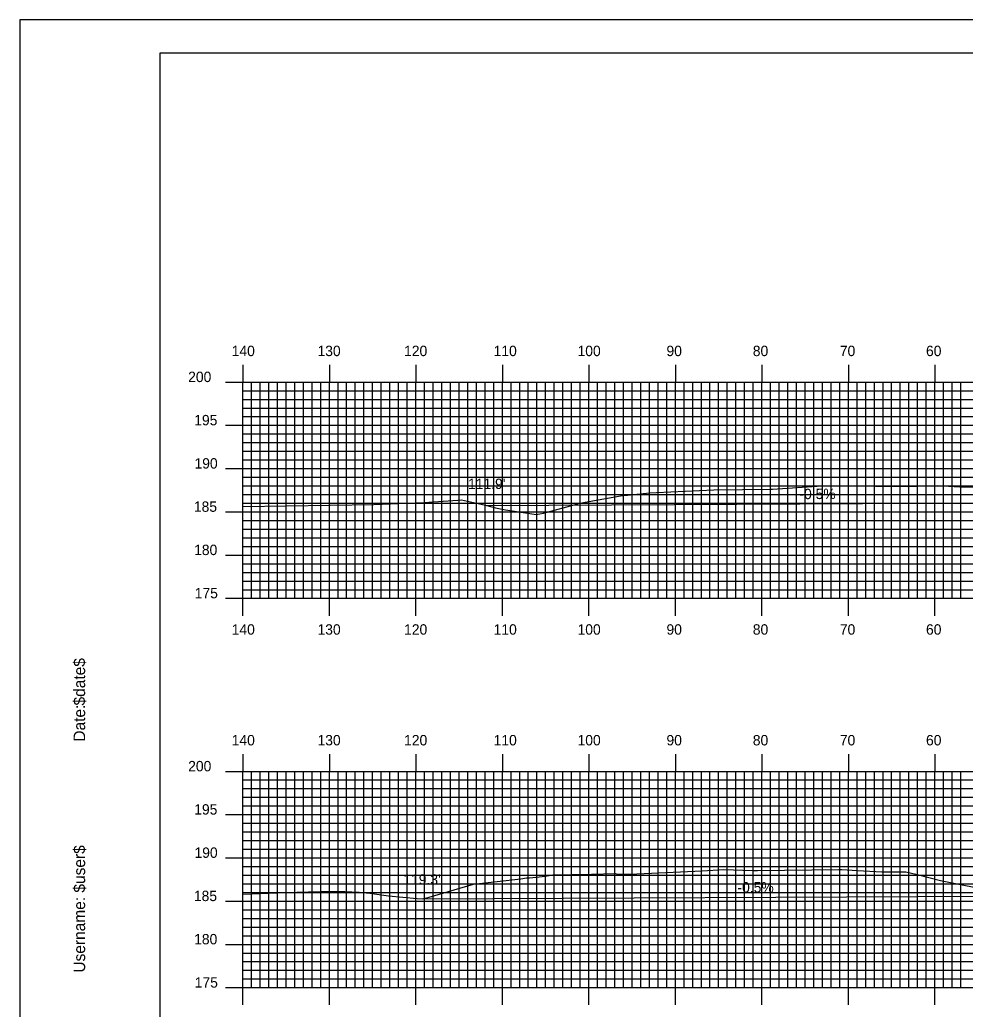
# Model space of a CAD drawing. Extents: x 1822785 to 1823129, y 442591 to 442811.
# Drawn here: x 1822785.5 to 1822894.8, y 442696.2 to 442810.5 of the extents above; entities that cross this region are included whole.
import ezdxf

# ---------------------------------------------------------------- set-up
doc = ezdxf.new("R2010")
doc.units = 0
for name, color, linetype in [('ANNOTATION', 7, 'Continuous'), ('BORDER', 7, 'Continuous'), ('D_Text_Standard', 7, 'Continuous'), ('H_V ANNOTATION', 7, 'Continuous'), ('MAJOR', 7, 'Continuous'), ('MINOR', 7, 'Continuous'), ('PLOT BOUNDARY', 7, 'Continuous'), ('S_Roadway_Centerline', 7, 'Continuous')]:
    doc.layers.add(name, color=color, linetype=linetype)

msp = doc.modelspace()

# ---------------------------------------------------------------- linework, layer by layer
at = {"layer": 'ANNOTATION'}
for p, q in [((1822839.41, 442754.41), (1822916.5, 442754.8)), ((1822832.01, 442708.93), (1822909.57, 442709.32))]:
    msp.add_line(p, q, dxfattribs=at)
at = {"layer": 'BORDER'}
msp.add_lwpolyline([(1822801.68, 442596.67), (1823121.68, 442596.67), (1823121.68, 442806.67), (1822801.68, 442806.67)], close=True, dxfattribs=at)
at = {"layer": 'MAJOR'}
for p, q in [((1822811.28, 442770.67), (1822811.28, 442768.67)), ((1822821.28, 442770.67), (1822821.28, 442768.67)), ((1822831.28, 442770.67), (1822831.28, 442768.67)), ((1822841.28, 442770.67), (1822841.28, 442768.67)), ((1822851.28, 442770.67), (1822851.28, 442768.67)), ((1822861.28, 442770.67), (1822861.28, 442768.67)), ((1822871.28, 442770.67), (1822871.28, 442768.67)), ((1822881.28, 442770.67), (1822881.28, 442768.67)), ((1822891.28, 442770.67), (1822891.28, 442768.67)), ((1822809.28, 442768.67), (1822811.28, 442768.67)), ((1822811.28, 442768.67), (1823091.28, 442768.67)), ((1822811.28, 442743.67), (1822811.28, 442768.67)), ((1822811.28, 442743.67), (1822811.28, 442768.67)), ((1822811.28, 442768.67), (1823091.28, 442768.67)), ((1822821.28, 442743.67), (1822821.28, 442768.67)), ((1822831.28, 442743.67), (1822831.28, 442768.67)), ((1822841.28, 442743.67), (1822841.28, 442768.67)), ((1822851.28, 442743.67), (1822851.28, 442768.67)), ((1822861.28, 442743.67), (1822861.28, 442768.67)), ((1822871.28, 442743.67), (1822871.28, 442768.67)), ((1822881.28, 442743.67), (1822881.28, 442768.67)), ((1822891.28, 442743.67), (1822891.28, 442768.67)), ((1822809.28, 442763.67), (1822811.28, 442763.67)), ((1822811.28, 442763.67), (1823091.28, 442763.67)), ((1822809.28, 442758.67), (1822811.28, 442758.67)), ((1822811.28, 442758.67), (1823091.28, 442758.67)), ((1822809.28, 442753.67), (1822811.28, 442753.67)), ((1822811.28, 442753.67), (1823091.28, 442753.67)), ((1822809.28, 442748.67), (1822811.28, 442748.67)), ((1822811.28, 442748.67), (1823091.28, 442748.67)), ((1822809.28, 442743.67), (1822811.28, 442743.67)), ((1822811.28, 442743.67), (1823091.28, 442743.67)), ((1822811.28, 442743.67), (1823091.28, 442743.67)), ((1822811.28, 442741.66), (1822811.28, 442743.67)), ((1822821.28, 442741.66), (1822821.28, 442743.67)), ((1822831.28, 442741.66), (1822831.28, 442743.67)), ((1822841.28, 442741.66), (1822841.28, 442743.67)), ((1822851.28, 442741.66), (1822851.28, 442743.67)), ((1822861.28, 442741.66), (1822861.28, 442743.67)), ((1822871.28, 442741.66), (1822871.28, 442743.67)), ((1822881.28, 442741.66), (1822881.28, 442743.67)), ((1822891.28, 442741.66), (1822891.28, 442743.67)), ((1822811.28, 442725.67), (1822811.28, 442723.67)), ((1822821.28, 442725.67), (1822821.28, 442723.67)), ((1822831.28, 442725.67), (1822831.28, 442723.67)), ((1822841.28, 442725.67), (1822841.28, 442723.67)), ((1822851.28, 442725.67), (1822851.28, 442723.67)), ((1822861.28, 442725.67), (1822861.28, 442723.67)), ((1822871.28, 442725.67), (1822871.28, 442723.67)), ((1822881.28, 442725.67), (1822881.28, 442723.67)), ((1822891.28, 442725.67), (1822891.28, 442723.67)), ((1822809.28, 442723.67), (1822811.28, 442723.67)), ((1822811.28, 442723.67), (1823091.28, 442723.67)), ((1822811.28, 442698.67), (1822811.28, 442723.67)), ((1822811.28, 442698.67), (1822811.28, 442723.67)), ((1822811.28, 442723.67), (1823091.28, 442723.67)), ((1822821.28, 442698.67), (1822821.28, 442723.67)), ((1822831.28, 442698.67), (1822831.28, 442723.67)), ((1822841.28, 442698.67), (1822841.28, 442723.67)), ((1822851.28, 442698.67), (1822851.28, 442723.67)), ((1822861.28, 442698.67), (1822861.28, 442723.67)), ((1822871.28, 442698.67), (1822871.28, 442723.67)), ((1822881.28, 442698.67), (1822881.28, 442723.67)), ((1822891.28, 442698.67), (1822891.28, 442723.67)), ((1822809.28, 442718.67), (1822811.28, 442718.67)), ((1822811.28, 442718.67), (1823091.28, 442718.67)), ((1822809.28, 442713.67), (1822811.28, 442713.67)), ((1822811.28, 442713.67), (1823091.28, 442713.67)), ((1822809.28, 442708.67), (1822811.28, 442708.67)), ((1822811.28, 442708.67), (1823091.28, 442708.67)), ((1822809.28, 442703.67), (1822811.28, 442703.67)), ((1822811.28, 442703.67), (1823091.28, 442703.67)), ((1822809.28, 442698.67), (1822811.28, 442698.67)), ((1822811.28, 442698.67), (1823091.28, 442698.67)), ((1822811.28, 442698.67), (1823091.28, 442698.67)), ((1822811.28, 442696.66), (1822811.28, 442698.67)), ((1822821.28, 442696.66), (1822821.28, 442698.67)), ((1822831.28, 442696.66), (1822831.28, 442698.67)), ((1822841.28, 442696.66), (1822841.28, 442698.67)), ((1822851.28, 442696.66), (1822851.28, 442698.67)), ((1822861.28, 442696.66), (1822861.28, 442698.67)), ((1822871.28, 442696.66), (1822871.28, 442698.67)), ((1822881.28, 442696.66), (1822881.28, 442698.67)), ((1822891.28, 442696.66), (1822891.28, 442698.67))]:
    msp.add_line(p, q, dxfattribs=at)
at = {"layer": 'MINOR'}
for p, q in [((1822811.28, 442767.67), (1823091.28, 442767.67)), ((1822811.28, 442767.67), (1822813.29, 442767.67)), ((1822812.28, 442743.67), (1822812.28, 442768.67)), ((1822813.28, 442743.67), (1822813.28, 442768.67)), ((1822814.28, 442743.67), (1822814.28, 442768.67)), ((1822815.28, 442743.67), (1822815.28, 442768.67)), ((1822816.28, 442743.67), (1822816.28, 442768.67)), ((1822817.28, 442743.67), (1822817.28, 442768.67)), ((1822818.28, 442743.67), (1822818.28, 442768.67)), ((1822819.28, 442743.67), (1822819.28, 442768.67)), ((1822820.28, 442743.67), (1822820.28, 442768.67)), ((1822822.28, 442743.67), (1822822.28, 442768.67)), ((1822823.28, 442743.67), (1822823.28, 442768.67)), ((1822824.28, 442743.67), (1822824.28, 442768.67)), ((1822825.28, 442743.67), (1822825.28, 442768.67)), ((1822826.28, 442743.67), (1822826.28, 442768.67)), ((1822827.28, 442743.67), (1822827.28, 442768.67)), ((1822828.28, 442743.67), (1822828.28, 442768.67)), ((1822829.28, 442743.67), (1822829.28, 442768.67)), ((1822830.28, 442743.67), (1822830.28, 442768.67)), ((1822832.28, 442743.67), (1822832.28, 442768.67)), ((1822833.28, 442743.67), (1822833.28, 442768.67)), ((1822834.28, 442743.67), (1822834.28, 442768.67)), ((1822835.28, 442743.67), (1822835.28, 442768.67)), ((1822836.28, 442743.67), (1822836.28, 442768.67)), ((1822837.28, 442743.67), (1822837.28, 442768.67)), ((1822838.28, 442743.67), (1822838.28, 442768.67)), ((1822839.28, 442743.67), (1822839.28, 442768.67)), ((1822840.28, 442743.67), (1822840.28, 442768.67)), ((1822842.28, 442743.67), (1822842.28, 442768.67)), ((1822843.28, 442743.67), (1822843.28, 442768.67)), ((1822844.28, 442743.67), (1822844.28, 442768.67)), ((1822845.28, 442743.67), (1822845.28, 442768.67)), ((1822846.28, 442743.67), (1822846.28, 442768.67)), ((1822847.28, 442743.67), (1822847.28, 442768.67)), ((1822848.28, 442743.67), (1822848.28, 442768.67)), ((1822849.28, 442743.67), (1822849.28, 442768.67)), ((1822850.28, 442743.67), (1822850.28, 442768.67)), ((1822852.28, 442743.67), (1822852.28, 442768.67)), ((1822853.28, 442743.67), (1822853.28, 442768.67)), ((1822854.28, 442743.67), (1822854.28, 442768.67)), ((1822855.28, 442743.67), (1822855.28, 442768.67)), ((1822856.28, 442743.67), (1822856.28, 442768.67)), ((1822857.28, 442743.67), (1822857.28, 442768.67)), ((1822858.28, 442743.67), (1822858.28, 442768.67)), ((1822859.28, 442743.67), (1822859.28, 442768.67)), ((1822860.28, 442743.67), (1822860.28, 442768.67)), ((1822862.28, 442743.67), (1822862.28, 442768.67)), ((1822863.28, 442743.67), (1822863.28, 442768.67)), ((1822864.28, 442743.67), (1822864.28, 442768.67)), ((1822865.28, 442743.67), (1822865.28, 442768.67)), ((1822866.28, 442743.67), (1822866.28, 442768.67)), ((1822867.28, 442743.67), (1822867.28, 442768.67)), ((1822868.28, 442743.67), (1822868.28, 442768.67)), ((1822869.28, 442743.67), (1822869.28, 442768.67)), ((1822870.28, 442743.67), (1822870.28, 442768.67)), ((1822872.28, 442743.67), (1822872.28, 442768.67)), ((1822873.28, 442743.67), (1822873.28, 442768.67)), ((1822874.28, 442743.67), (1822874.28, 442768.67)), ((1822875.28, 442743.67), (1822875.28, 442768.67)), ((1822876.28, 442743.67), (1822876.28, 442768.67)), ((1822877.28, 442743.67), (1822877.28, 442768.67)), ((1822878.28, 442743.67), (1822878.28, 442768.67)), ((1822879.28, 442743.67), (1822879.28, 442768.67)), ((1822880.28, 442743.67), (1822880.28, 442768.67)), ((1822882.28, 442743.67), (1822882.28, 442768.67)), ((1822883.28, 442743.67), (1822883.28, 442768.67)), ((1822884.28, 442743.67), (1822884.28, 442768.67)), ((1822885.28, 442743.67), (1822885.28, 442768.67)), ((1822886.28, 442743.67), (1822886.28, 442768.67)), ((1822887.28, 442743.67), (1822887.28, 442768.67)), ((1822888.28, 442743.67), (1822888.28, 442768.67)), ((1822889.28, 442743.67), (1822889.28, 442768.67)), ((1822890.28, 442743.67), (1822890.28, 442768.67)), ((1822892.28, 442743.67), (1822892.28, 442768.67)), ((1822893.28, 442743.67), (1822893.28, 442768.67)), ((1822894.28, 442743.67), (1822894.28, 442768.67)), ((1822811.28, 442766.67), (1823091.28, 442766.67)), ((1822811.28, 442766.67), (1822813.29, 442766.67)), ((1822811.28, 442765.67), (1823091.28, 442765.67)), ((1822811.28, 442765.67), (1822813.29, 442765.67)), ((1822811.28, 442764.67), (1823091.28, 442764.67)), ((1822811.28, 442764.67), (1822813.29, 442764.67)), ((1822811.28, 442762.67), (1823091.28, 442762.67)), ((1822811.28, 442762.67), (1822813.29, 442762.67)), ((1822811.28, 442761.67), (1823091.28, 442761.67)), ((1822811.28, 442761.67), (1822813.29, 442761.67)), ((1822811.28, 442760.67), (1823091.28, 442760.67)), ((1822811.28, 442760.67), (1822813.29, 442760.67)), ((1822811.28, 442759.67), (1823091.28, 442759.67)), ((1822811.28, 442759.67), (1822813.29, 442759.67)), ((1822811.28, 442757.67), (1823091.28, 442757.67)), ((1822811.28, 442757.67), (1822813.29, 442757.67)), ((1822811.28, 442756.67), (1823091.28, 442756.67)), ((1822811.28, 442756.67), (1822813.29, 442756.67)), ((1822811.28, 442755.67), (1823091.28, 442755.67)), ((1822811.28, 442755.67), (1822813.29, 442755.67)), ((1822811.28, 442754.67), (1823091.28, 442754.67)), ((1822811.28, 442754.67), (1822813.29, 442754.67)), ((1822811.28, 442752.67), (1823091.28, 442752.67)), ((1822811.28, 442752.67), (1822813.29, 442752.67)), ((1822811.28, 442751.67), (1823091.28, 442751.67)), ((1822811.28, 442751.67), (1822813.29, 442751.67)), ((1822811.28, 442750.67), (1823091.28, 442750.67)), ((1822811.28, 442750.67), (1822813.29, 442750.67)), ((1822811.28, 442749.67), (1823091.28, 442749.67)), ((1822811.28, 442749.67), (1822813.29, 442749.67)), ((1822811.28, 442747.67), (1823091.28, 442747.67)), ((1822811.28, 442747.67), (1822813.29, 442747.67)), ((1822811.28, 442746.67), (1823091.28, 442746.67)), ((1822811.28, 442746.67), (1822813.29, 442746.67)), ((1822811.28, 442745.67), (1823091.28, 442745.67)), ((1822811.28, 442745.67), (1822813.29, 442745.67)), ((1822811.28, 442744.67), (1823091.28, 442744.67)), ((1822811.28, 442744.67), (1822813.29, 442744.67)), ((1822812.28, 442698.67), (1822812.28, 442723.67)), ((1822813.28, 442698.67), (1822813.28, 442723.67)), ((1822814.28, 442698.67), (1822814.28, 442723.67)), ((1822815.28, 442698.67), (1822815.28, 442723.67)), ((1822816.28, 442698.67), (1822816.28, 442723.67)), ((1822817.28, 442698.67), (1822817.28, 442723.67)), ((1822818.28, 442698.67), (1822818.28, 442723.67)), ((1822819.28, 442698.67), (1822819.28, 442723.67)), ((1822820.28, 442698.67), (1822820.28, 442723.67)), ((1822822.28, 442698.67), (1822822.28, 442723.67)), ((1822823.28, 442698.67), (1822823.28, 442723.67)), ((1822824.28, 442698.67), (1822824.28, 442723.67)), ((1822825.28, 442698.67), (1822825.28, 442723.67)), ((1822826.28, 442698.67), (1822826.28, 442723.67)), ((1822827.28, 442698.67), (1822827.28, 442723.67)), ((1822828.28, 442698.67), (1822828.28, 442723.67)), ((1822829.28, 442698.67), (1822829.28, 442723.67)), ((1822830.28, 442698.67), (1822830.28, 442723.67)), ((1822832.28, 442698.67), (1822832.28, 442723.67)), ((1822833.28, 442698.67), (1822833.28, 442723.67)), ((1822834.28, 442698.67), (1822834.28, 442723.67)), ((1822835.28, 442698.67), (1822835.28, 442723.67)), ((1822836.28, 442698.67), (1822836.28, 442723.67)), ((1822837.28, 442698.67), (1822837.28, 442723.67)), ((1822838.28, 442698.67), (1822838.28, 442723.67)), ((1822839.28, 442698.67), (1822839.28, 442723.67)), ((1822840.28, 442698.67), (1822840.28, 442723.67)), ((1822842.28, 442698.67), (1822842.28, 442723.67)), ((1822843.28, 442698.67), (1822843.28, 442723.67)), ((1822844.28, 442698.67), (1822844.28, 442723.67)), ((1822845.28, 442698.67), (1822845.28, 442723.67)), ((1822846.28, 442698.67), (1822846.28, 442723.67)), ((1822847.28, 442698.67), (1822847.28, 442723.67)), ((1822848.28, 442698.67), (1822848.28, 442723.67)), ((1822849.28, 442698.67), (1822849.28, 442723.67)), ((1822850.28, 442698.67), (1822850.28, 442723.67)), ((1822852.28, 442698.67), (1822852.28, 442723.67)), ((1822853.28, 442698.67), (1822853.28, 442723.67)), ((1822854.28, 442698.67), (1822854.28, 442723.67)), ((1822855.28, 442698.67), (1822855.28, 442723.67)), ((1822856.28, 442698.67), (1822856.28, 442723.67)), ((1822857.28, 442698.67), (1822857.28, 442723.67)), ((1822858.28, 442698.67), (1822858.28, 442723.67)), ((1822859.28, 442698.67), (1822859.28, 442723.67)), ((1822860.28, 442698.67), (1822860.28, 442723.67)), ((1822862.28, 442698.67), (1822862.28, 442723.67)), ((1822863.28, 442698.67), (1822863.28, 442723.67)), ((1822864.28, 442698.67), (1822864.28, 442723.67)), ((1822865.28, 442698.67), (1822865.28, 442723.67)), ((1822866.28, 442698.67), (1822866.28, 442723.67)), ((1822867.28, 442698.67), (1822867.28, 442723.67)), ((1822868.28, 442698.67), (1822868.28, 442723.67)), ((1822869.28, 442698.67), (1822869.28, 442723.67)), ((1822870.28, 442698.67), (1822870.28, 442723.67)), ((1822872.28, 442698.67), (1822872.28, 442723.67)), ((1822873.28, 442698.67), (1822873.28, 442723.67)), ((1822874.28, 442698.67), (1822874.28, 442723.67)), ((1822875.28, 442698.67), (1822875.28, 442723.67)), ((1822876.28, 442698.67), (1822876.28, 442723.67)), ((1822877.28, 442698.67), (1822877.28, 442723.67)), ((1822878.28, 442698.67), (1822878.28, 442723.67)), ((1822879.28, 442698.67), (1822879.28, 442723.67)), ((1822880.28, 442698.67), (1822880.28, 442723.67)), ((1822882.28, 442698.67), (1822882.28, 442723.67)), ((1822883.28, 442698.67), (1822883.28, 442723.67)), ((1822884.28, 442698.67), (1822884.28, 442723.67)), ((1822885.28, 442698.67), (1822885.28, 442723.67)), ((1822886.28, 442698.67), (1822886.28, 442723.67)), ((1822887.28, 442698.67), (1822887.28, 442723.67)), ((1822888.28, 442698.67), (1822888.28, 442723.67)), ((1822889.28, 442698.67), (1822889.28, 442723.67)), ((1822890.28, 442698.67), (1822890.28, 442723.67)), ((1822892.28, 442698.67), (1822892.28, 442723.67)), ((1822893.28, 442698.67), (1822893.28, 442723.67)), ((1822894.28, 442698.67), (1822894.28, 442723.67)), ((1822811.28, 442722.67), (1823091.28, 442722.67)), ((1822811.28, 442722.67), (1822813.29, 442722.67)), ((1822811.28, 442721.67), (1823091.28, 442721.67)), ((1822811.28, 442721.67), (1822813.29, 442721.67)), ((1822811.28, 442720.67), (1823091.28, 442720.67)), ((1822811.28, 442720.67), (1822813.29, 442720.67)), ((1822811.28, 442719.67), (1823091.28, 442719.67)), ((1822811.28, 442719.67), (1822813.29, 442719.67)), ((1822811.28, 442717.67), (1823091.28, 442717.67)), ((1822811.28, 442717.67), (1822813.29, 442717.67)), ((1822811.28, 442716.67), (1823091.28, 442716.67)), ((1822811.28, 442716.67), (1822813.29, 442716.67)), ((1822811.28, 442715.67), (1823091.28, 442715.67)), ((1822811.28, 442715.67), (1822813.29, 442715.67)), ((1822811.28, 442714.67), (1823091.28, 442714.67)), ((1822811.28, 442714.67), (1822813.29, 442714.67)), ((1822811.28, 442712.67), (1823091.28, 442712.67)), ((1822811.28, 442712.67), (1822813.29, 442712.67)), ((1822811.28, 442711.67), (1823091.28, 442711.67)), ((1822811.28, 442711.67), (1822813.29, 442711.67)), ((1822811.28, 442710.67), (1823091.28, 442710.67)), ((1822811.28, 442710.67), (1822813.29, 442710.67)), ((1822811.28, 442709.67), (1823091.28, 442709.67)), ((1822811.28, 442709.67), (1822813.29, 442709.67)), ((1822811.28, 442707.67), (1823091.28, 442707.67)), ((1822811.28, 442707.67), (1822813.29, 442707.67)), ((1822811.28, 442706.67), (1823091.28, 442706.67)), ((1822811.28, 442706.67), (1822813.29, 442706.67)), ((1822811.28, 442705.67), (1823091.28, 442705.67)), ((1822811.28, 442705.67), (1822813.29, 442705.67)), ((1822811.28, 442704.67), (1823091.28, 442704.67)), ((1822811.28, 442704.67), (1822813.29, 442704.67)), ((1822811.28, 442702.67), (1823091.28, 442702.67)), ((1822811.28, 442702.67), (1822813.29, 442702.67)), ((1822811.28, 442701.67), (1823091.28, 442701.67)), ((1822811.28, 442701.67), (1822813.29, 442701.67)), ((1822811.28, 442700.67), (1823091.28, 442700.67)), ((1822811.28, 442700.67), (1822813.29, 442700.67)), ((1822811.28, 442699.67), (1823091.28, 442699.67)), ((1822811.28, 442699.67), (1822813.29, 442699.67))]:
    msp.add_line(p, q, dxfattribs=at)
at = {"layer": 'PLOT BOUNDARY'}
msp.add_lwpolyline([(1822785.5, 442590.55), (1823125.5, 442590.55), (1823125.5, 442810.55), (1822785.5, 442810.55)], close=True, dxfattribs=at)
at = {"layer": 'S_Roadway_Centerline'}
for points in [[(1822811.28, 442754.27), (1822826.41, 442754.52), (1822832.2, 442754.74), (1822836.14, 442755), (1822836.55, 442755.06), (1822839.34, 442754.43), (1822840.47, 442754.14), (1822841.64, 442753.91), (1822844.44, 442753.46), (1822845.2, 442753.36), (1822846.03, 442753.52), (1822849.99, 442754.58), (1822850.07, 442754.63), (1822850.86, 442754.77), (1822854.93, 442755.51), (1822855.73, 442755.59), (1822857.56, 442755.8), (1822858.31, 442755.88), (1822859.1, 442755.91), (1822865.73, 442756.2), (1822872.34, 442756.28), (1822872.37, 442756.28), (1822872.5, 442756.29), (1822878.23, 442756.69), (1822878.42, 442756.68), (1822880.63, 442756.66), (1822888.16, 442756.59), (1822891.53, 442756.72), (1822894.15, 442756.56), (1822897.24, 442756.49)], [(1822811.28, 442709.48), (1822816.16, 442709.68), (1822820.23, 442709.78), (1822822.21, 442709.83), (1822824.71, 442709.69), (1822825.97, 442709.6), (1822828.13, 442709.29), (1822831.42, 442708.98), (1822832.01, 442708.93), (1822832.82, 442709.13), (1822837.94, 442710.61), (1822843.4, 442711.24), (1822844.08, 442711.35), (1822844.42, 442711.36), (1822846.28, 442711.54), (1822847.11, 442711.69), (1822851.6, 442711.78), (1822854.33, 442711.87), (1822854.59, 442711.8), (1822856.84, 442711.84), (1822864.36, 442712.15), (1822866.88, 442712.34), (1822870.19, 442712.2), (1822870.77, 442712.2), (1822880.18, 442712.31), (1822880.52, 442712.32), (1822882.33, 442712.21), (1822885.16, 442712.05), (1822887.93, 442712.07), (1822889.09, 442711.78), (1822890.58, 442711.38), (1822891.93, 442711.04), (1822898.31, 442709.78)]]:
    msp.add_lwpolyline(points, dxfattribs=at)

# ---------------------------------------------------------------- texts
at = {"layer": 'ANNOTATION'}
for p in [(1822875.62, 442755.13), (1822868.46, 442709.65)]:
    msp.add_text('-0.5%', height=1.2, rotation=0.2865, dxfattribs=at).set_placement(p)
at = {"layer": 'BORDER'}
for s, p in [('$date$', (1822793.05, 442731.28)), ('Date:', (1822793.05, 442727.1)), ('$user$', (1822793.05, 442709.65)), ('Username:', (1822793.05, 442700.4))]:
    msp.add_text(s, height=1.339, rotation=90, dxfattribs=at).set_placement(p)
at = {"layer": 'D_Text_Standard'}
for s, p in [("111.9'", (1822837.31, 442756.31)), ("119.3'", (1822829.83, 442710.57))]:
    msp.add_text(s, height=1.2, dxfattribs=at).set_placement(p)
at = {"layer": 'H_V ANNOTATION'}
for s, p in [('140', (1822809.99, 442771.67)), ('130', (1822819.91, 442771.67)), ('120', (1822829.92, 442771.67)), ('110', (1822840.27, 442771.67)), ('100', (1822849.97, 442771.67)), ('90', (1822860.25, 442771.67)), ('80', (1822870.23, 442771.67)), ('70', (1822880.29, 442771.67)), ('60', (1822890.25, 442771.67)), ('200', (1822804.96, 442768.67)), ('195', (1822805.66, 442763.67)), ('190', (1822805.69, 442758.67)), ('185', (1822805.62, 442753.67)), ('180', (1822805.65, 442748.67)), ('175', (1822805.72, 442743.67)), ('140', (1822809.99, 442739.47)), ('130', (1822819.91, 442739.47)), ('120', (1822829.92, 442739.47)), ('110', (1822840.27, 442739.47)), ('100', (1822849.97, 442739.47)), ('90', (1822860.25, 442739.47)), ('80', (1822870.23, 442739.47)), ('70', (1822880.29, 442739.47)), ('60', (1822890.25, 442739.47)), ('140', (1822809.99, 442726.67)), ('130', (1822819.91, 442726.67)), ('120', (1822829.92, 442726.67)), ('110', (1822840.27, 442726.67)), ('100', (1822849.97, 442726.67)), ('90', (1822860.25, 442726.67)), ('80', (1822870.23, 442726.67)), ('70', (1822880.29, 442726.67)), ('60', (1822890.25, 442726.67)), ('200', (1822804.96, 442723.67)), ('195', (1822805.66, 442718.67)), ('190', (1822805.69, 442713.67)), ('185', (1822805.62, 442708.67)), ('180', (1822805.65, 442703.67)), ('175', (1822805.72, 442698.67))]:
    msp.add_text(s, height=1.2, dxfattribs=at).set_placement(p)
at = {"layer": 'MAJOR'}
for p in [(1822811.27, 442743.67), (1822811.27, 442698.67)]:
    msp.add_text('-', height=0.012, dxfattribs=at).set_placement(p)
at = {"layer": 'S_Roadway_Centerline'}
for s, p in [('C', (1822878.23, 442756.69)), ('L', (1822878.22, 442756.68)), ('C', (1822866.87, 442712.34)), ('L', (1822866.87, 442712.33))]:
    msp.add_text(s, height=0.0146, dxfattribs=at).set_placement(p)

doc.saveas('drawing.dxf')
